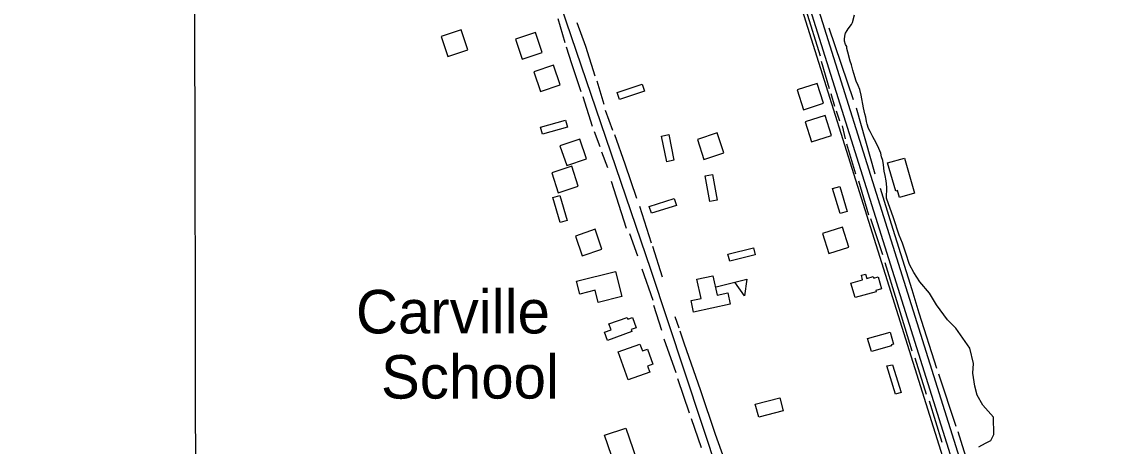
# Model space of a CAD drawing. Extents: x 3324104 to 3361979, y 612876 to 638273.
# Drawn here: x 3354198 to 3356280, y 624575 to 625385 of the extents above; entities that cross this region are included whole.
import ezdxf

# ---------------------------------------------------------------- set-up
doc = ezdxf.new("R2010")
doc.units = 0
for name, color, linetype in [('V-BLDG-IDEN', 7, 'Continuous'), ('V-BLDG-OTLN', 7, 'Continuous'), ('V-GRID-MAJR', 7, 'Continuous'), ('V-ROAD-CNTR', 7, 'Continuous'), ('V-SITE-VEGE', 7, 'Continuous'), ('V-TOPO-SHOR', 7, 'Continuous')]:
    doc.layers.add(name, color=color, linetype=linetype)

msp = doc.modelspace()

# ---------------------------------------------------------------- linework, layer by layer
at = {"layer": 'V-BLDG-OTLN'}
msp.add_line((3355522.7, 624879.5), (3355580.9, 624894), dxfattribs=at)
for points in [[(3355048.9, 625331.5), (3355036.1, 625369.4), (3354998.2, 625356.7), (3355011, 625318.8)], [(3355190.6, 625326.6), (3355177.8, 625364.5), (3355139.9, 625351.8), (3355152.7, 625313.8)], [(3355225.4, 625264.5), (3355212.6, 625302.4), (3355174.7, 625289.7), (3355187.4, 625251.7)], [(3355386, 625252.7), (3355338.6, 625236.8), (3355334.1, 625250.1), (3355381.5, 625266)], [(3355727.3, 625229.4), (3355715.1, 625267.5), (3355677, 625255.2), (3355689.2, 625217.1)], [(3355239.4, 625184.1), (3355191.3, 625170.4), (3355187.4, 625183.9), (3355235.5, 625197.5)], [(3355742.7, 625168), (3355730.4, 625206.1), (3355692.4, 625193.9), (3355704.6, 625155.8)], [(3355275.5, 625123.4), (3355262.7, 625161.3), (3355224.8, 625148.5), (3355237.6, 625110.6)], [(3355432.1, 625169.7), (3355442, 625120.7), (3355428.3, 625117.9), (3355418.4, 625166.9)], [(3355486.8, 625160.3), (3355499.4, 625122.3), (3355537.4, 625134.9), (3355524.8, 625172.9)], [(3355881.7, 625124.9), (3355900.7, 625057.7), (3355872.5, 625049.7), (3355868.8, 625062.8), (3355865.1, 625061.7), (3355849.8, 625115.8)], [(3355259.5, 625071.1), (3355247.2, 625109.2), (3355209.1, 625096.9), (3355221.4, 625058.8)], [(3355515.5, 625093.7), (3355524.3, 625044.5), (3355510.6, 625042), (3355501.7, 625091.2)], [(3355758.3, 625070.8), (3355772.7, 625023), (3355759.3, 625018.9), (3355744.9, 625066.8)], [(3355224.3, 625053.7), (3355238.4, 625005.8), (3355225, 625001.8), (3355210.9, 625049.8)], [(3355446.8, 625034.6), (3355399.1, 625019.5), (3355394.9, 625032.8), (3355442.6, 625047.9)], [(3355304.9, 624951.1), (3355292.2, 624989), (3355254.3, 624976.2), (3355267, 624938.3)], [(3355775.6, 624955.2), (3355763.4, 624993.3), (3355725.3, 624981.1), (3355737.5, 624943)], [(3355597.1, 624940.3), (3355548.7, 624928.1), (3355545.2, 624941.6), (3355593.7, 624953.9)], [(3355297.8, 624849.4), (3355291.9, 624872.7), (3355262.7, 624865.4), (3355256.6, 624889.9), (3355330.9, 624908.7), (3355343, 624860.8)], [(3355494.1, 624857.2), (3355486.1, 624893.8), (3355516.5, 624900.3), (3355524.5, 624863.2), (3355544.7, 624867.6), (3355549.3, 624846.2), (3355479.6, 624831.1), (3355474.8, 624853)], [(3355580.9, 624894), (3355577, 624862.1), (3355558.5, 624888.4)], [(3355827.6, 624870), (3355787.6, 624858.7), (3355779.7, 624886.5), (3355802.1, 624892.8), (3355799.8, 624901.2), (3355807.6, 624903.4), (3355809.9, 624895.2), (3355822.4, 624898.7), (3355823.2, 624895.9), (3355831.7, 624898.3), (3355838.2, 624875.4), (3355827, 624872.2)], [(3355318.2, 624808.5), (3355352.8, 624820.9), (3355354, 624817.7), (3355362.9, 624820.8), (3355370, 624801.1), (3355360.3, 624797.6), (3355361.7, 624793.7), (3355315.4, 624777), (3355309.7, 624792.8), (3355322.2, 624797.3)], [(3355811.5, 624780.8), (3355854.8, 624792.9), (3355861.2, 624770), (3355856.3, 624768.6), (3355856.9, 624766.6), (3355819.1, 624756.1)], [(3355354.7, 624701.7), (3355335.5, 624755), (3355377.1, 624770), (3355381.9, 624756.9), (3355391.4, 624760.3), (3355401.7, 624731.6), (3355392, 624728.1), (3355396.2, 624716.6)], [(3355859.2, 624730.6), (3355875.4, 624677.5), (3355864.9, 624674.3), (3355848.2, 624728.8)], [(3355597.3, 624655.5), (3355644, 624667.7), (3355650.5, 624642.6), (3355603.9, 624630.4)], [(3355350.2, 624609.8), (3355370.5, 624550.5), (3355330.3, 624536.8), (3355310, 624596.1)]]:
    msp.add_lwpolyline(points, close=True, dxfattribs=at)
at = {"layer": 'V-GRID-MAJR'}
msp.add_spline([(3354542.6, 618302.9), (3354530.3, 624362.2), (3354517.9, 630423.5), (3354505.6, 636484.8), (3354505.6, 636486.7)], degree=3, dxfattribs=at)
at = {"layer": 'V-ROAD-CNTR'}
for points in [[(3352021.7, 630244.3), (3352651.6, 629771.2), (3353683.7, 628994.4), (3353943.5, 628801.2), (3354006.8, 628745.3), (3354059.1, 628688.9), (3354091.2, 628651.6), (3354110.9, 628626.3), (3354134.3, 628589.9), (3354154.4, 628550.8), (3354177.8, 628494.1), (3354236, 628339.1), (3354477.5, 627603.8), (3354685.1, 626987.4), (3354756.4, 626784.5), (3354959, 626210.1), (3355169.5, 625581.4), (3355397.3, 624912.7), (3355884.2, 623441.8)], [(3356251.3, 623612.2), (3355260.1, 626766.4)], [(3356265.7, 623616.7), (3355274.4, 626770.8)], [(3356280, 623621.2), (3355288.7, 626775.3)]]:
    msp.add_lwpolyline(points, dxfattribs=at)
at = {"layer": 'V-SITE-VEGE'}
for points in [[(3355821.4, 625165.5), (3355816.4, 625175.8), (3355813.3, 625181.3), (3355810.6, 625189.7), (3355809.5, 625194.8), (3355808, 625203.1), (3355806.2, 625209.4), (3355803.5, 625220.5), (3355799.1, 625245), (3355796.5, 625255.6), (3355793.8, 625263.5), (3355790, 625271.5), (3355785.1, 625286.5), (3355783.6, 625292.8), (3355780.9, 625302.7), (3355778.3, 625309.8), (3355773.7, 625327.2), (3355772.2, 625333.9), (3355771.9, 625337.5), (3355769.6, 625341.8), (3355767.3, 625348.2), (3355767.4, 625352.5), (3355768.7, 625361.2), (3355769.1, 625363.1), (3355772.3, 625368.6), (3355774.3, 625371.3), (3355780.7, 625379.5), (3355782.7, 625383.8), (3355786.4, 625398)], [(3356023.7, 624574.2), (3356036.2, 624581.2), (3356046.6, 624586.1), (3356052.2, 624597.3), (3356051.4, 624630.8), (3356031.1, 624653.7), (3356020.6, 624672.6), (3356016.4, 624690), (3356012.1, 624714.4), (3356013.4, 624733.2), (3356006.4, 624762.5), (3355979.8, 624800.1), (3355963.7, 624816.1), (3355942.7, 624844.7), (3355929.3, 624867), (3355911.1, 624888.5), (3355899.9, 624906.7), (3355891.5, 624922), (3355884.5, 624943.6), (3355878.1, 624962.4), (3355871.8, 624977.7), (3355861.2, 625011.2), (3355847.9, 625048.2), (3355848.1, 625069), (3355847.4, 625075.7), (3355846.7, 625081.3), (3355844.9, 625091.9), (3355843.4, 625099.8), (3355842, 625112.1), (3355840.5, 625120.3), (3355838.2, 625127.5), (3355836.7, 625134.2), (3355832.9, 625143.3), (3355829.5, 625150), (3355824.8, 625159.5), (3355821.4, 625165.5)]]:
    msp.add_lwpolyline(points, dxfattribs=at)
at = {"layer": 'V-TOPO-SHOR'}
for p, q in [((3355721.4, 625319.1), (3355694.6, 625407.1)), ((3355234.6, 625344.8), (3355221.6, 625390.6)), ((3355784.9, 625235.9), (3355738.4, 625372.9)), ((3355739.1, 625256.9), (3355723.5, 625309.3)), ((3355309.2, 625227.4), (3355295.5, 625271.7)), ((3355286.6, 625185.2), (3355269.2, 625241.8)), ((3355748.9, 625223.4), (3355741.9, 625247.8)), ((3355825.9, 625094.1), (3355790.5, 625219.9)), ((3355325.8, 625177.6), (3355311.5, 625215.7)), ((3355758.8, 625195.4), (3355752.2, 625214.1)), ((3355301.6, 625146.3), (3355290.8, 625174.9)), ((3355769.4, 625161.9), (3355763.7, 625186.3)), ((3355316, 625106.1), (3355304.5, 625136.1)), ((3355789.2, 625094.1), (3355772.2, 625151.4)), ((3355351.4, 624990.7), (3355323.2, 625080.1)), ((3355813.9, 625015.8), (3355794.8, 625080.8)), ((3355399.2, 624962.7), (3355376.8, 625032.3)), ((3355840.7, 624940.4), (3355817.4, 625008.8)), ((3355373.5, 624937.6), (3355357.7, 624980.5)), ((3355420.1, 624897.8), (3355402, 624955.9)), ((3355402.3, 624853), (3355381.5, 624913)), ((3355419, 624795.6), (3355403.8, 624843.4)), ((3355451.9, 624800.3), (3355444.6, 624822.1)), ((3355446.4, 624715.1), (3355423.4, 624779.2)), ((3355923.9, 624674.1), (3355902.1, 624743.3)), ((3355471.6, 624638), (3355449.3, 624703.5)), ((3355980.4, 624612.6), (3355947.2, 624712.5)), ((3355953.6, 624581.9), (3355929.6, 624660.9)), ((3355494.6, 624571.9), (3355475.9, 624627.1))]:
    msp.add_line(p, q, dxfattribs=at)
for points in [[(3355291.9, 625281.3), (3355273.8, 625337.9), (3355257.3, 625382.9)], [(3355264.9, 625251.4), (3355247.6, 625304.6), (3355237.5, 625336.7)], [(3355371.1, 625048), (3355348.8, 625113.5), (3355329.3, 625169.4)], [(3355943.7, 624723.7), (3355909.8, 624829.2), (3355896.4, 624873.3), (3355856.9, 624999), (3355836.4, 625066.8)], [(3355896.4, 624756.6), (3355867.5, 624852.3), (3355844.9, 624925)], [(3355546.8, 624526.7), (3355521.6, 624597.7), (3355493.5, 624680.9), (3355461.9, 624771.6), (3355454, 624794.8)], [(3356120.8, 624167.5), (3356098.9, 624239.5), (3356053.1, 624376.4), (3356004.4, 624537.2), (3355984.6, 624602.8)]]:
    msp.add_lwpolyline(points, dxfattribs=at)

# ---------------------------------------------------------------- texts
at = {"layer": 'V-BLDG-IDEN'}
for s, p in [('Carville', (3354835.6, 624790.3)), ('School', (3354883.4, 624666))]:
    msp.add_text(s, height=83, dxfattribs=at).set_placement(p)

doc.saveas('drawing.dxf')
